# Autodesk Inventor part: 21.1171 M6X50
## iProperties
Created: 2006-02
Part Number: 21.1171 M6X50
Material: Steel, Mild
Description: Cylinder Head Cap Screw
Document SubType Name: Modeling
Standard: DIN 7984
Designer: Andy Moles
Standards Organization: DIN
Language: en-US
Size Designation: M6 x 40
Categories: <MemberInstance><Categories><Category DisplayName="Fasteners" InternalName="e4da775c-781d-43d5-af7c-5136215cf5a6" Mnemonic="FSTN"><Category DisplayName="Bolts"
Density: 1 g/cm^3
Author: Andy Moles
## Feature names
1. Body [Revolution]
2. Slot [Extrusion]
3. Fillet1
4. Chamfer1
